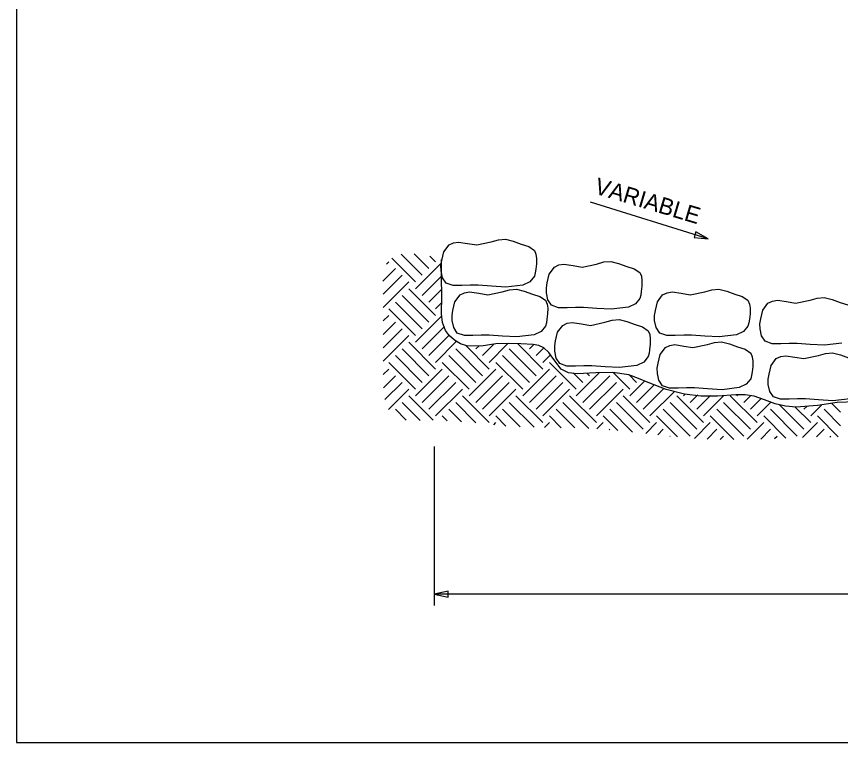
# Model space of a CAD drawing. Extents: x -439.1 to -407.9, y -458.1 to -436.2.
# Drawn here: x -439.11 to -431.65, y -458.05 to -451.48 of the extents above; entities that cross this region are included whole.
import ezdxf

# ---------------------------------------------------------------- set-up
doc = ezdxf.new("R2010")
doc.units = 0
doc.layers.add('Draft_Named_Boundary', color=7, linetype='Continuous')
doc.layers.add('Level 4', color=7, linetype='Continuous')

msp = doc.modelspace()

# ---------------------------------------------------------------- linework, layer by layer
at = {"layer": 'Draft_Named_Boundary'}
msp.add_lwpolyline([(-439.109, -458.0508), (-407.859, -458.0508), (-407.859, -437.6758), (-439.109, -437.6758)], close=True, dxfattribs=at)
at = {"layer": 'Level 4'}
for p, q in [((-432.8485, -453.4922), (-433.9141, -453.161)), ((-435.4981, -453.8828), (-435.7135, -453.6673)), ((-435.4374, -453.8222), (-435.6284, -453.6312)), ((-435.3768, -453.7615), (-435.5105, -453.6279)), ((-435.3162, -453.7009), (-435.3672, -453.6499)), ((-435.7933, -453.8749), (-435.6799, -453.7615)), ((-435.7599, -453.7203), (-435.7405, -453.7009)), ((-435.4981, -453.9434), (-435.2637, -453.709)), ((-435.7916, -453.9944), (-435.6193, -453.8222)), ((-435.4374, -454.004), (-435.2629, -453.8295)), ((-435.7903, -454.1144), (-435.5587, -453.8828)), ((-435.3162, -454.1858), (-435.5587, -453.9434)), ((-435.3768, -454.0646), (-435.2604, -453.9482)), ((-435.4374, -454.3071), (-435.6799, -454.0646)), ((-435.3768, -454.2465), (-435.6193, -454.004)), ((-435.4981, -454.3677), (-435.7405, -454.1252)), ((-435.3162, -454.1252), (-435.2614, -454.0704)), ((-435.7903, -454.2356), (-435.7405, -454.1858)), ((-435.4981, -454.4283), (-435.2588, -454.189)), ((-435.7903, -454.3568), (-435.6799, -454.2465)), ((-435.4374, -454.4889), (-435.2345, -454.286)), ((-435.7903, -454.4781), (-435.6193, -454.3071)), ((-435.7903, -454.5993), (-435.5587, -454.3677)), ((-435.3768, -454.5495), (-435.1891, -454.3618)), ((-435.3162, -454.6708), (-435.5587, -454.4283)), ((-435.3162, -454.6101), (-435.1256, -454.4195)), ((-435.3768, -454.7314), (-435.6193, -454.4889)), ((-434.8919, -454.7314), (-435.1344, -454.4889)), ((-434.8313, -454.6708), (-435.0464, -454.4556)), ((-434.9525, -454.4889), (-434.9264, -454.4628)), ((-434.8919, -454.5495), (-434.7889, -454.4465)), ((-434.8313, -454.6101), (-434.6652, -454.444)), ((-434.407, -454.7314), (-434.6495, -454.4889)), ((-434.3464, -454.6708), (-434.5731, -454.444)), ((-434.4676, -454.4889), (-434.4283, -454.4496)), ((-434.407, -454.5495), (-434.3363, -454.4788)), ((-435.4374, -454.792), (-435.6799, -454.5495)), ((-434.9525, -454.792), (-435.195, -454.5495)), ((-434.4676, -454.792), (-434.7101, -454.5495)), ((-434.3464, -454.6101), (-434.2772, -454.541)), ((-435.4981, -454.8526), (-435.7405, -454.6101)), ((-435.0131, -454.8526), (-435.2556, -454.6101)), ((-434.5282, -454.8526), (-434.7707, -454.6101)), ((-434.0433, -454.8526), (-434.2858, -454.6101)), ((-435.7903, -454.7205), (-435.7405, -454.6708)), ((-435.7879, -454.8394), (-435.6799, -454.7314)), ((-435.4981, -454.9132), (-435.2556, -454.6708)), ((-435.4374, -454.9738), (-435.195, -454.7314)), ((-435.0131, -454.9132), (-434.7707, -454.6708)), ((-434.9525, -454.9738), (-434.7101, -454.7314)), ((-434.5282, -454.9132), (-434.2858, -454.6708)), ((-434.4676, -454.9738), (-434.2252, -454.7314)), ((-433.9827, -454.792), (-434.0703, -454.7044)), ((-434.0433, -454.9132), (-433.8349, -454.7048)), ((-433.9827, -454.9738), (-433.7402, -454.7314)), ((-433.9221, -454.7314), (-433.9434, -454.7101)), ((-433.5584, -454.8526), (-433.7096, -454.7015)), ((-433.4978, -454.792), (-433.5655, -454.7243)), ((-435.7744, -454.9471), (-435.6193, -454.792)), ((-435.3768, -455.0344), (-435.1344, -454.792)), ((-434.8919, -455.0344), (-434.6495, -454.792)), ((-434.407, -455.0344), (-434.1646, -454.792)), ((-433.9221, -455.0344), (-433.6796, -454.792)), ((-433.5584, -454.9132), (-433.4255, -454.7803)), ((-433.4978, -454.9738), (-433.3381, -454.8141)), ((-435.7421, -455.0361), (-435.5587, -454.8526)), ((-435.3162, -455.0951), (-435.0738, -454.8526)), ((-434.8313, -455.0951), (-434.5889, -454.8526)), ((-434.3464, -455.0951), (-434.1039, -454.8526)), ((-433.8615, -455.0951), (-433.619, -454.8526)), ((-433.4372, -455.0344), (-433.2502, -454.8474)), ((-433.3766, -455.0951), (-433.1555, -454.874)), ((-435.3377, -455.1342), (-435.5587, -454.9132)), ((-434.8313, -455.1557), (-435.0738, -454.9132)), ((-434.3464, -455.1557), (-434.5889, -454.9132)), ((-433.8615, -455.1557), (-434.1039, -454.9132)), ((-433.3766, -455.1557), (-433.619, -454.9132)), ((-432.8917, -455.1557), (-433.1341, -454.9132)), ((-433.0735, -454.9132), (-433.0581, -454.8978)), ((-433.0129, -454.9738), (-432.9436, -454.9046)), ((-432.9523, -455.0344), (-432.8291, -454.9113)), ((-432.8917, -455.0951), (-432.7074, -454.9108)), ((-432.4067, -455.1557), (-432.6492, -454.9132)), ((-432.5886, -454.9132), (-432.5797, -454.9044)), ((-432.528, -454.9738), (-432.4668, -454.9126)), ((-432.4674, -455.0344), (-432.369, -454.936)), ((-435.5823, -455.1321), (-435.6799, -455.0344)), ((-435.4552, -455.1379), (-435.6193, -454.9738)), ((-435.0823, -455.1471), (-435.195, -455.0344)), ((-434.9506, -455.1576), (-435.1344, -454.9738)), ((-434.5502, -455.1944), (-434.7101, -455.0344)), ((-434.4253, -455.198), (-434.6495, -454.9738)), ((-434.0554, -455.2042), (-434.2252, -455.0344)), ((-433.9297, -455.2087), (-434.1646, -454.9738)), ((-433.5336, -455.2411), (-433.7402, -455.0344)), ((-433.4372, -455.2163), (-433.6796, -454.9738)), ((-433.0129, -455.2769), (-433.2553, -455.0344)), ((-432.9523, -455.2163), (-433.1947, -454.9738)), ((-432.528, -455.2769), (-432.7704, -455.0344)), ((-432.4674, -455.2163), (-432.7098, -454.9738)), ((-432.4067, -455.0951), (-432.2819, -454.9702)), ((-432.0431, -455.2769), (-432.2855, -455.0344)), ((-431.9824, -455.2163), (-432.2085, -454.9903)), ((-431.9218, -455.1557), (-432.0641, -455.0134)), ((-431.9824, -455.0344), (-431.9567, -455.0086)), ((-431.9218, -455.0951), (-431.8234, -454.9966)), ((-431.6515, -455.1836), (-431.8006, -455.0344)), ((-431.6515, -455.0623), (-431.7316, -454.9822)), ((-435.21, -455.1407), (-435.2556, -455.0951)), ((-434.6794, -455.1864), (-434.7707, -455.0951)), ((-434.1789, -455.202), (-434.2858, -455.0951)), ((-433.6682, -455.2277), (-433.8009, -455.0951)), ((-433.1256, -455.2854), (-433.3159, -455.0951)), ((-432.6183, -455.3078), (-432.831, -455.0951)), ((-432.1456, -455.2956), (-432.3461, -455.0951)), ((-431.6722, -455.284), (-431.8612, -455.0951)), ((-434.7905, -455.1755), (-434.7707, -455.1557)), ((-434.3299, -455.1998), (-434.2858, -455.1557)), ((-433.8582, -455.213), (-433.8009, -455.1557)), ((-433.4146, -455.2543), (-433.3159, -455.1557)), ((-432.9743, -455.2989), (-432.831, -455.1557)), ((-432.4967, -455.3062), (-432.3461, -455.1557)), ((-431.9944, -455.2889), (-431.8612, -455.1557)), ((-433.7449, -455.2209), (-433.7402, -455.2163)), ((-433.3054, -455.2664), (-433.2553, -455.2163)), ((-432.8596, -455.3054), (-432.7704, -455.2163)), ((-432.3738, -455.3046), (-432.2855, -455.2163)), ((-431.869, -455.2846), (-431.8006, -455.2163)), ((-433.1961, -455.2783), (-433.1947, -455.2769)), ((-432.7423, -455.3094), (-432.7098, -455.2769)), ((-432.2481, -455.3001), (-432.2249, -455.2769)), ((-431.7474, -455.2843), (-431.74, -455.2769)), ((-435.3292, -455.3705), (-435.3292, -456.8116)), ((-422.0298, -456.7088), (-435.3292, -456.7088))]:
    msp.add_line(p, q, dxfattribs=at)
for points in [[(-432.9771, -453.4797), (-432.8485, -453.4922), (-432.9615, -453.4295)], [(-432.9771, -453.4797), (-432.8485, -453.4922), (-432.9615, -453.4295)], [(-435.2599, -453.6891), (-435.2415, -453.6105), (-435.1942, -453.5479), (-435.1538, -453.5283), (-435.1088, -453.5216), (-435.026, -453.5339), (-434.9445, -453.5479), (-434.8132, -453.5199), (-434.7482, -453.5011), (-434.6849, -453.4953), (-434.6143, -453.5133), (-434.5403, -453.5413), (-434.4732, -453.5622), (-434.422, -453.5971), (-434.4076, -453.6308), (-434.4023, -453.6694), (-434.4033, -453.719), (-434.4089, -453.768), (-434.4136, -453.8002), (-434.422, -453.8304), (-434.4619, -453.8803), (-434.5254, -453.9104), (-434.6816, -453.929), (-434.8116, -453.9218), (-434.9313, -453.9126), (-435.003, -453.9127), (-435.0792, -453.9159), (-435.1563, -453.9159), (-435.2205, -453.8929), (-435.2527, -453.8439), (-435.2665, -453.7811), (-435.2673, -453.7342), (-435.2599, -453.6891)], [(-434.3063, -453.8899), (-434.2879, -453.8113), (-434.2405, -453.7486), (-434.2002, -453.7291), (-434.1551, -453.7223), (-434.0723, -453.7347), (-433.9908, -453.7486), (-433.8595, -453.7207), (-433.7945, -453.7019), (-433.7312, -453.696), (-433.6606, -453.7141), (-433.5867, -453.742), (-433.5195, -453.7629), (-433.4684, -453.7979), (-433.454, -453.8315), (-433.4486, -453.8702), (-433.4496, -453.9198), (-433.4552, -453.9688), (-433.46, -454.001), (-433.4684, -454.0312), (-433.5083, -454.0811), (-433.5718, -454.1112), (-433.7279, -454.1298), (-433.8579, -454.1225), (-433.9777, -454.1133), (-434.0494, -454.1134), (-434.1255, -454.1166), (-434.2026, -454.1166), (-434.2668, -454.0936), (-434.299, -454.0447), (-434.3128, -453.9819), (-434.3136, -453.935), (-434.3063, -453.8899)], [(-435.1595, -454.1409), (-435.1412, -454.0623), (-435.0938, -453.9996), (-435.0534, -453.98), (-435.0084, -453.9733), (-434.9256, -453.9856), (-434.8441, -453.9996), (-434.7128, -453.9717), (-434.6478, -453.9529), (-434.5845, -453.947), (-434.5139, -453.965), (-434.4399, -453.993), (-434.3728, -454.0139), (-434.3216, -454.0489), (-434.3072, -454.0825), (-434.3019, -454.1212), (-434.3029, -454.1708), (-434.3085, -454.2197), (-434.3133, -454.2519), (-434.3216, -454.2822), (-434.3616, -454.3321), (-434.425, -454.3621), (-434.5812, -454.3807), (-434.7112, -454.3735), (-434.8309, -454.3643), (-434.9026, -454.3644), (-434.9788, -454.3676), (-435.0559, -454.3676), (-435.1201, -454.3446), (-435.1523, -454.2956), (-435.1661, -454.2329), (-435.1669, -454.186), (-435.1595, -454.1409)], [(-433.3275, -454.1409), (-433.3092, -454.0623), (-433.2618, -453.9996), (-433.2214, -453.98), (-433.1764, -453.9733), (-433.0936, -453.9856), (-433.0121, -453.9996), (-432.8808, -453.9717), (-432.8158, -453.9529), (-432.7525, -453.947), (-432.6819, -453.965), (-432.6079, -453.993), (-432.5408, -454.0139), (-432.4896, -454.0489), (-432.4752, -454.0825), (-432.4699, -454.1212), (-432.4709, -454.1708), (-432.4765, -454.2197), (-432.4813, -454.2519), (-432.4896, -454.2822), (-432.5296, -454.3321), (-432.593, -454.3621), (-432.7492, -454.3807), (-432.8792, -454.3735), (-432.9989, -454.3643), (-433.0706, -454.3644), (-433.1468, -454.3676), (-433.2239, -454.3676), (-433.2881, -454.3446), (-433.3203, -454.2956), (-433.3341, -454.2329), (-433.3349, -454.186), (-433.3275, -454.1409)], [(-434.231, -454.4169), (-434.2126, -454.3383), (-434.1653, -454.2756), (-434.1249, -454.2561), (-434.0798, -454.2493), (-433.997, -454.2617), (-433.9155, -454.2756), (-433.7842, -454.2477), (-433.7192, -454.2289), (-433.6559, -454.2231), (-433.5854, -454.2411), (-433.5114, -454.2691), (-433.4442, -454.2899), (-433.3931, -454.3249), (-433.3787, -454.3585), (-433.3734, -454.3972), (-433.3744, -454.4468), (-433.3799, -454.4958), (-433.3847, -454.528), (-433.3931, -454.5582), (-433.433, -454.6081), (-433.4965, -454.6382), (-433.6527, -454.6568), (-433.7826, -454.6496), (-433.9024, -454.6404), (-433.9741, -454.6405), (-434.0503, -454.6436), (-434.1274, -454.6436), (-434.1915, -454.6206), (-434.2238, -454.5717), (-434.2375, -454.5089), (-434.2383, -454.462), (-434.231, -454.4169)], [(-433.3024, -454.6177), (-433.2841, -454.5391), (-433.2367, -454.4764), (-433.1963, -454.4569), (-433.1513, -454.4501), (-433.0685, -454.4625), (-432.987, -454.4764), (-432.8557, -454.4485), (-432.7907, -454.4297), (-432.7274, -454.4238), (-432.6568, -454.4419), (-432.5828, -454.4698), (-432.5157, -454.4907), (-432.4645, -454.5257), (-432.4501, -454.5593), (-432.4448, -454.598), (-432.4458, -454.6476), (-432.4514, -454.6966), (-432.4562, -454.7288), (-432.4645, -454.759), (-432.5045, -454.8089), (-432.5679, -454.8389), (-432.7241, -454.8576), (-432.8541, -454.8503), (-432.9738, -454.8411), (-433.0455, -454.8412), (-433.1217, -454.8444), (-433.1988, -454.8444), (-433.263, -454.8214), (-433.2952, -454.7724), (-433.309, -454.7097), (-433.3098, -454.6628), (-433.3024, -454.6177)], [(-435.2027, -456.6825), (-435.3292, -456.7088), (-435.2027, -456.735)]]:
    msp.add_lwpolyline(points, close=True, dxfattribs=at)
for points in [[(-435.1443, -454.4109), (-435.1902, -454.3701), (-435.2255, -454.3219), (-435.2529, -454.2499), (-435.2631, -454.1717), (-435.2604, -454.008), (-435.2626, -453.842), (-435.2633, -453.6786)], [(-431.6394, -454.4374), (-431.7956, -454.456), (-431.9255, -454.4488), (-432.0453, -454.4396), (-432.117, -454.4397), (-432.1932, -454.4429), (-432.2703, -454.4429), (-432.3344, -454.4199), (-432.3667, -454.3709), (-432.3804, -454.3082), (-432.3812, -454.2613), (-432.3739, -454.2162), (-432.3739, -454.2162), (-432.3555, -454.1375), (-432.3082, -454.0749), (-432.2678, -454.0553), (-432.2227, -454.0486), (-432.1399, -454.0609), (-432.0584, -454.0749), (-431.9271, -454.047), (-431.8621, -454.0281), (-431.7988, -454.0223), (-431.7283, -454.0403), (-431.6543, -454.0683), (-431.5871, -454.0892)], [(-431.5102, -454.9673), (-431.6833, -454.9746), (-431.859, -455.0022), (-432.0537, -455.0151), (-432.1495, -455.0066), (-432.2428, -454.9848), (-432.3386, -454.948), (-432.4346, -454.915), (-432.5152, -454.9033), (-432.5979, -454.903), (-432.7661, -454.915), (-432.9156, -454.9149), (-433.0626, -454.8975), (-433.2305, -454.8549), (-433.394, -454.7929), (-433.4809, -454.7549), (-433.5684, -454.7231), (-433.7117, -454.7011), (-433.865, -454.7057), (-434.0355, -454.7152), (-434.1133, -454.704), (-434.1789, -454.6708), (-434.2558, -454.5727), (-434.2925, -454.5204), (-434.3359, -454.4789), (-434.3816, -454.4579), (-434.4336, -454.4479), (-434.5452, -454.444), (-434.6603, -454.4408), (-434.772, -454.444), (-434.9029, -454.463), (-435.0336, -454.4615), (-435.091, -454.4421), (-435.1443, -454.4109)], [(-431.5641, -454.9393), (-431.7203, -454.9579), (-431.8502, -454.9507), (-431.97, -454.9415), (-432.0417, -454.9416), (-432.1179, -454.9448), (-432.195, -454.9448), (-432.2592, -454.9218), (-432.2914, -454.8728), (-432.3052, -454.8101), (-432.306, -454.7632), (-432.2986, -454.7181), (-432.2986, -454.7181), (-432.2802, -454.6395), (-432.2329, -454.5768), (-432.1925, -454.5572), (-432.1474, -454.5505), (-432.0646, -454.5628), (-431.9831, -454.5768), (-431.8518, -454.5489), (-431.7868, -454.5301), (-431.7236, -454.5242), (-431.653, -454.5422), (-431.579, -454.5702)]]:
    msp.add_lwpolyline(points, dxfattribs=at)

# ---------------------------------------------------------------- texts
msp.add_text('VARIABLE', height=0.15, rotation=343.36532, dxfattribs=at).set_placement((-433.8878, -453.0799))

doc.saveas('drawing.dxf')
